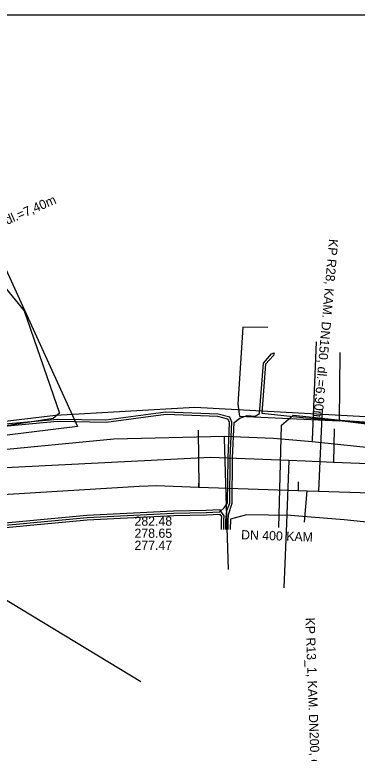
# Model space of a CAD drawing. Extents: x -600309 to -598967, y -1161267 to -1160292.
# Drawn here: x -599791.1 to -599761.3, y -1160356.5 to -1160292.3 of the extents above; entities that cross this region are included whole.
import ezdxf

# ---------------------------------------------------------------- set-up
doc = ezdxf.new("R2010")
doc.units = 0
for name, color, linetype in [('Vrstva 1', 7, 'Continuous'), ('Vrstva 12', 7, 'Continuous'), ('Vrstva 13', 7, 'Continuous'), ('Vrstva 16', 7, 'Continuous'), ('Vrstva 42', 7, 'Continuous'), ('Vrstva 55', 7, 'Continuous'), ('Vrstva 63', 7, 'Continuous'), ('Vrstva 9', 7, 'Continuous')]:
    doc.layers.add(name, color=color, linetype=linetype)

msp = doc.modelspace()

# ---------------------------------------------------------------- linework, layer by layer
at = {"layer": 'Vrstva 1'}
msp.add_lwpolyline([(-599775.115, -1160328.428), (-599775.049, -1160333.348)], dxfattribs=at)
at = {"layer": 'Vrstva 12'}
for points in [[(-599792.87, -1160314.87), (-599790.23, -1160318.07), (-599787.16, -1160326.95), (-599787.71, -1160327.41), (-599795.17, -1160328.57), (-599798.9, -1160329.16)], [(-599769.04, -1160319.52), (-599771.23, -1160319.47), (-599771.67, -1160326.16), (-599771.51, -1160327.2), (-599762.81, -1160327.61)], [(-599762.81, -1160327.61), (-599762.75, -1160321.69)], [(-599761.85, -1160327.72), (-599762.81, -1160327.61)], [(-599698.73, -1160336.13), (-599698.88, -1160336.14), (-599706.13, -1160336.61), (-599706.4, -1160336.63), (-599706.35, -1160338.29), (-599706.67, -1160338.98), (-599710.08, -1160341.48), (-599711.3, -1160341.62), (-599718.55, -1160338.58), (-599731.46, -1160333.88), (-599742.6, -1160330.92), (-599747.62, -1160329.83), (-599751.55, -1160329.08), (-599757.44, -1160328.28), (-599761.85, -1160327.72)]]:
    msp.add_lwpolyline(points, dxfattribs=at)
at = {"layer": 'Vrstva 13'}
for points in [[(-599792.27, -1160313.5), (-599785.59, -1160328.1), (-599794.09, -1160329.16), (-599795.25, -1160329.29)], [(-599765.18, -1160329.44), (-599765.174, -1160329.279), (-599764.822, -1160320.768)], [(-599703.28, -1160352.81), (-599706.29, -1160350.37), (-599709.031, -1160348.188), (-599710.105, -1160343.732), (-599713.375, -1160342.312), (-599719.058, -1160339.8), (-599731.415, -1160335.463), (-599741.66, -1160332.93), (-599753.57, -1160330.65), (-599765.18, -1160329.44), (-599768.556, -1160329.155), (-599772.843, -1160328.976), (-599782.43, -1160329.2), (-599793.27, -1160330.24), (-599801.007, -1160331.389), (-599801.239, -1160331.715), (-599803.02, -1160335.63), (-599806.693, -1160336.994), (-599809.526, -1160338.024), (-599811.51, -1160338.7)], [(-599772.843, -1160328.976), (-599772.84, -1160329.14), (-599772.68, -1160335.03), (-599772.495, -1160340.541)], [(-599797.19, -1160339.93), (-599780.09, -1160350.26)]]:
    msp.add_lwpolyline(points, dxfattribs=at)
at = {"layer": 'Vrstva 16'}
for points in [[(-599763.272, -1160328.318), (-599763.336, -1160331.225)], [(-599702.27, -1160348.9), (-599702.81, -1160348.59), (-599703.01, -1160348.47), (-599713.25, -1160343.48), (-599731.4, -1160336.4), (-599752.85, -1160331.63), (-599763.336, -1160331.225), (-599765.81, -1160331.13), (-599767.22, -1160331.07), (-599774.03, -1160330.81), (-599799.91, -1160332.11), (-599800.24, -1160332.08), (-599800.41, -1160332.08)], [(-599767.22, -1160331.07), (-599767.42, -1160336.51), (-599767.65, -1160342.11)]]:
    msp.add_lwpolyline(points, dxfattribs=at)
at = {"layer": 'Vrstva 42'}
for points in [[(-599772.51, -1160337.06), (-599772.51, -1160336.29), (-599772.455, -1160335.759), (-599772.15, -1160334.782), (-599772.11, -1160330.845), (-599771.97, -1160327.749), (-599771.48, -1160327.4), (-599770.86, -1160327.16), (-599770.16, -1160327.2), (-599769.764, -1160326.986), (-599769.437, -1160322.619), (-599768.717, -1160321.804), (-599768.51, -1160321.72), (-599768.567, -1160321.936), (-599769.243, -1160322.701), (-599769.561, -1160326.941), (-599765.74, -1160327.37), (-599760.25, -1160327.72)], [(-599772.71, -1160337.06), (-599772.71, -1160336.29), (-599772.622, -1160335.414), (-599772.35, -1160334.78), (-599772.31, -1160330.84), (-599772.17, -1160327.74), (-599772.363, -1160327.298), (-599773.376, -1160327.05), (-599777.925, -1160326.86), (-599783.126, -1160327.55), (-599787.334, -1160327.49), (-599794.852, -1160328.171), (-599801.17, -1160329.11), (-599802.567, -1160329.199), (-599803.991, -1160328.724), (-599804.923, -1160327.589), (-599805.108, -1160327.117), (-599805.095, -1160327.011), (-599805.006, -1160326.973)], [(-599792.81, -1160336.77), (-599788.8, -1160336.4), (-599784.76, -1160336.01), (-599777.24, -1160335.63), (-599774.4, -1160335.58), (-599773.24, -1160335.52), (-599773.163, -1160335.457), (-599772.833, -1160335.188), (-599772.55, -1160334.778), (-599772.51, -1160330.834), (-599772.37, -1160327.731), (-599772.537, -1160327.462), (-599773.404, -1160327.25), (-599777.915, -1160327.06), (-599783.114, -1160327.75), (-599787.326, -1160327.69), (-599794.828, -1160328.369)], [(-599792.834, -1160336.571), (-599788.819, -1160336.201), (-599784.775, -1160335.81), (-599777.247, -1160335.43), (-599774.407, -1160335.38), (-599773.257, -1160335.321), (-599773.163, -1160335.457), (-599772.872, -1160335.878), (-599772.905, -1160336.233), (-599772.91, -1160337.06)], [(-599791.526, -1160359.481), (-599795.267, -1160350.95), (-599797.888, -1160344.979), (-599798.078, -1160344.066), (-599796.147, -1160340.851), (-599794.173, -1160337.356), (-599793.753, -1160337.112), (-599792.786, -1160336.969), (-599788.781, -1160336.599), (-599784.745, -1160336.21), (-599777.233, -1160335.83), (-599774.393, -1160335.78), (-599773.224, -1160335.719), (-599773.08, -1160335.928), (-599773.11, -1160336.29), (-599773.11, -1160337.06)], [(-599706.172, -1160360.854), (-599706.217, -1160360.826), (-599706.86, -1160360.34), (-599706.91, -1160359.36), (-599711.2, -1160351.54), (-599713.7, -1160350.31), (-599718.62, -1160347.89), (-599722.647, -1160346.228), (-599722.716, -1160346.379), (-599722.89, -1160346.52), (-599722.898, -1160346.297), (-599722.832, -1160346.152), (-599728.71, -1160343.72), (-599733.77, -1160342.03), (-599739.46, -1160340.35), (-599742.78, -1160339.44), (-599746.73, -1160338.59), (-599751.87, -1160337.57), (-599757.08, -1160336.77), (-599762.4, -1160336.23), (-599767.09, -1160335.84), (-599770.89, -1160335.77), (-599772.302, -1160336.174), (-599772.31, -1160337.06)]]:
    msp.add_lwpolyline(points, dxfattribs=at)
at = {"layer": 'Vrstva 55'}
for points in [[(-599786.91, -1160401.141), (-599787.47, -1160401.13), (-599788.06, -1160400.36), (-599787.11, -1160399.83), (-599778.02, -1160396.88), (-599778.414, -1160395.77), (-599780.47, -1160389.65), (-599785.58, -1160378.15), (-599787.376, -1160373.868), (-599790.252, -1160367.01), (-599790.52, -1160366.37), (-599793.771, -1160358.433), (-599795.53, -1160354.14), (-599802.08, -1160339.79), (-599804.867, -1160332.786), (-599805.45, -1160331.32), (-599805.25, -1160330.04), (-599804.09, -1160329.36), (-599802.69, -1160329.03), (-599799.694, -1160328.568), (-599787.507, -1160327.13), (-599775.397, -1160326.445), (-599760.552, -1160327.235)], [(-599768.09, -1160336.89), (-599767.85, -1160328), (-599766.84, -1160327.13), (-599750.82, -1160328.8), (-599742.924, -1160330.101), (-599736.88, -1160332.09), (-599729.98, -1160334.03), (-599723.27, -1160336.38), (-599719.99, -1160337.52), (-599716.334, -1160338.792), (-599710.81, -1160341.74), (-599708.98, -1160340.521)], [(-599768.09, -1160336.89), (-599767.85, -1160328), (-599766.84, -1160327.13), (-599750.82, -1160328.8), (-599736.88, -1160332.09), (-599729.98, -1160334.03), (-599723.27, -1160336.38), (-599719.99, -1160337.52), (-599710.81, -1160341.74), (-599706.98, -1160339.19), (-599697.945, -1160339.17)]]:
    msp.add_lwpolyline(points, dxfattribs=at)
at = {"layer": 'Vrstva 63'}
msp.add_lwpolyline([(-600308.541, -1160292.347), (-598967.108, -1160292.347), (-598967.108, -1161267.031), (-600308.541, -1161267.031)], close=True, dxfattribs=at)
at = {"layer": 'Vrstva 9'}
for p, q in [((-599764.33, -1160326.59), (-599764.65, -1160333.725)), ((-599775.044, -1160332.623), (-599775.071, -1160333.372)), ((-599766.399, -1160332.912), (-599766.426, -1160333.661)), ((-599765.87, -1160336.43), (-599765.626, -1160333.686))]:
    msp.add_line(p, q, dxfattribs=at)
for points in [[(-599809.26, -1160335.06), (-599808.74, -1160335.02), (-599800.656, -1160334.526), (-599780.24, -1160333.28), (-599779.44, -1160333.26)], [(-599779.44, -1160333.26), (-599778.74, -1160333.25), (-599775.07, -1160333.37), (-599766.43, -1160333.66), (-599765.626, -1160333.686), (-599764.65, -1160333.725), (-599751.95, -1160334.14), (-599751.2, -1160334.18)]]:
    msp.add_lwpolyline(points, dxfattribs=at)

# ---------------------------------------------------------------- texts
at = {"layer": 'Vrstva 12'}
for s, rotation, p in [('KP 16, KAM. DN150, dl.=7,40m', 23.51859, (-599801.191, -1160314.724)), ('KP R28, KAM. DN150, dl.=6,90m', 264.99055, (-599763.721, -1160311.801)), ('DN 400 KAM', 358.0776, (-599771.384, -1160337.905)), ('KP R13_1, KAM. DN200, dl.=2,80m', 272.00312, (-599765.777, -1160344.724))]:
    msp.add_text(s, height=0.8, rotation=rotation, dxfattribs=at).set_placement(p)
for s, p in [('282.48', (-599780.642, -1160336.73)), ('278.65', (-599780.642, -1160337.78)), ('277.47', (-599780.642, -1160338.83))]:
    msp.add_text(s, height=0.8, dxfattribs=at).set_placement(p)

doc.saveas('drawing.dxf')
